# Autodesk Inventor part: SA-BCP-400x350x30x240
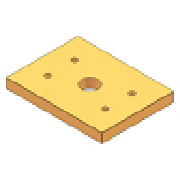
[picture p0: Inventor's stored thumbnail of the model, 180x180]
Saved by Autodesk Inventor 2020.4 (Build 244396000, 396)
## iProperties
Created: 2019-01
Part Number: SA-BCP-400x350x30x240
Material: S 55 C
Description: Bottom Clamping Plate
Document SubType Name: Modeling
Designer: mel
Standard Revision: 1
Manufacturer: FUTABA
Language: fr-FR
Size Designation: 400x350x30x240
Categories: <MemberInstance><Categories><Category DisplayName="Moule" InternalName="349578f2-f4d4-4954-8c09-8e99297a61c0" Mnemonic="MOLD"><Category DisplayName="Plaque de m
Density: 7.85 g/cm^3
Appearance: Orange (Pale)
IsCustomPart: 1
Author: mel
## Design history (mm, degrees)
sketch "Sketch1"
  geometry: L1 (-175, 200)-(175, 200); L2 (175, 200)-(175, -200); L3 (175, -200)-(-175, -200); L4 (-175, -200)-(-175, 200); C1 r 17.5 at (0, 0); 4 further points
  constraints: 8 end point, 2 midpoint, 2 parallel, 1 centre point, 1 coincident, 1 horizontal, 1 horizontal alignment, 1 perpendicular, 1 vertical alignment
  dimensions: "d72" = 350 distance between parallel lines of L2 L4 (= W_); "d73" = 400 distance between parallel lines of L3 L1 (= L); "d74" = 35 diameter of C1 (= dB); "d75" = 120 horizontal distance of point (0, 0) point (-120, 119) (= 0.5 x S1_W); "d76" = 119 vertical distance of point (0, 0) point (-120, 119) (= 0.5 x S1_L)
hole "Hole1" sketch "Sketch1" diameter "d79" = 16 (= S1_d1); stored, may be unused: countersink angle "d83" = 90 deg, drill point angle "d85" = 0 deg; dims "d80" = 6, "d81" = 24 (= S1_d2), "d82" = 15 (= S1_k), "d84" = 30 (= H_)
pattern_linear "Rectangular Pattern1" dims "d88" = 119 (computed from S1_L, Ns), "d91" = 240 (computed from S1_W, Nw)
chamfer "Chamfer1" distance "d94" = 0.5; stored, may be unused: second distance "d95" = 2, angle "d96" = 45 deg
body "Solid1"
extrude "Extrusion1" new body sketch "Sketch1" distance "d77" = 30 (= H_); taper "d78" = 0 deg
extrude "Extrusion2" cut sketch "Sketch1" distance "d92" = 30 (= H_); taper "d93" = 0 deg
other parameters: "L" = 400 [user parameter; used in 1 equation term], "W_" = 350 [user parameter; used in 1 equation term], "H_" = 30 [user parameter; used in 3 equation terms], "S1_d1" = 16 [user parameter; used in 1 equation term], "S1_d2" = 24 [user parameter; used in 1 equation term], "S1_k" = 15 [user parameter; used in 1 equation term], "S1_L" = 238 [user parameter; used in 2 equation terms], "dB" = 35 [user parameter; used in 1 equation term]
